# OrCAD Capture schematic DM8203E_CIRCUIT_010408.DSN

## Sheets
1 DM9162: size B; note: www.jhongtech.com    qq:441635295
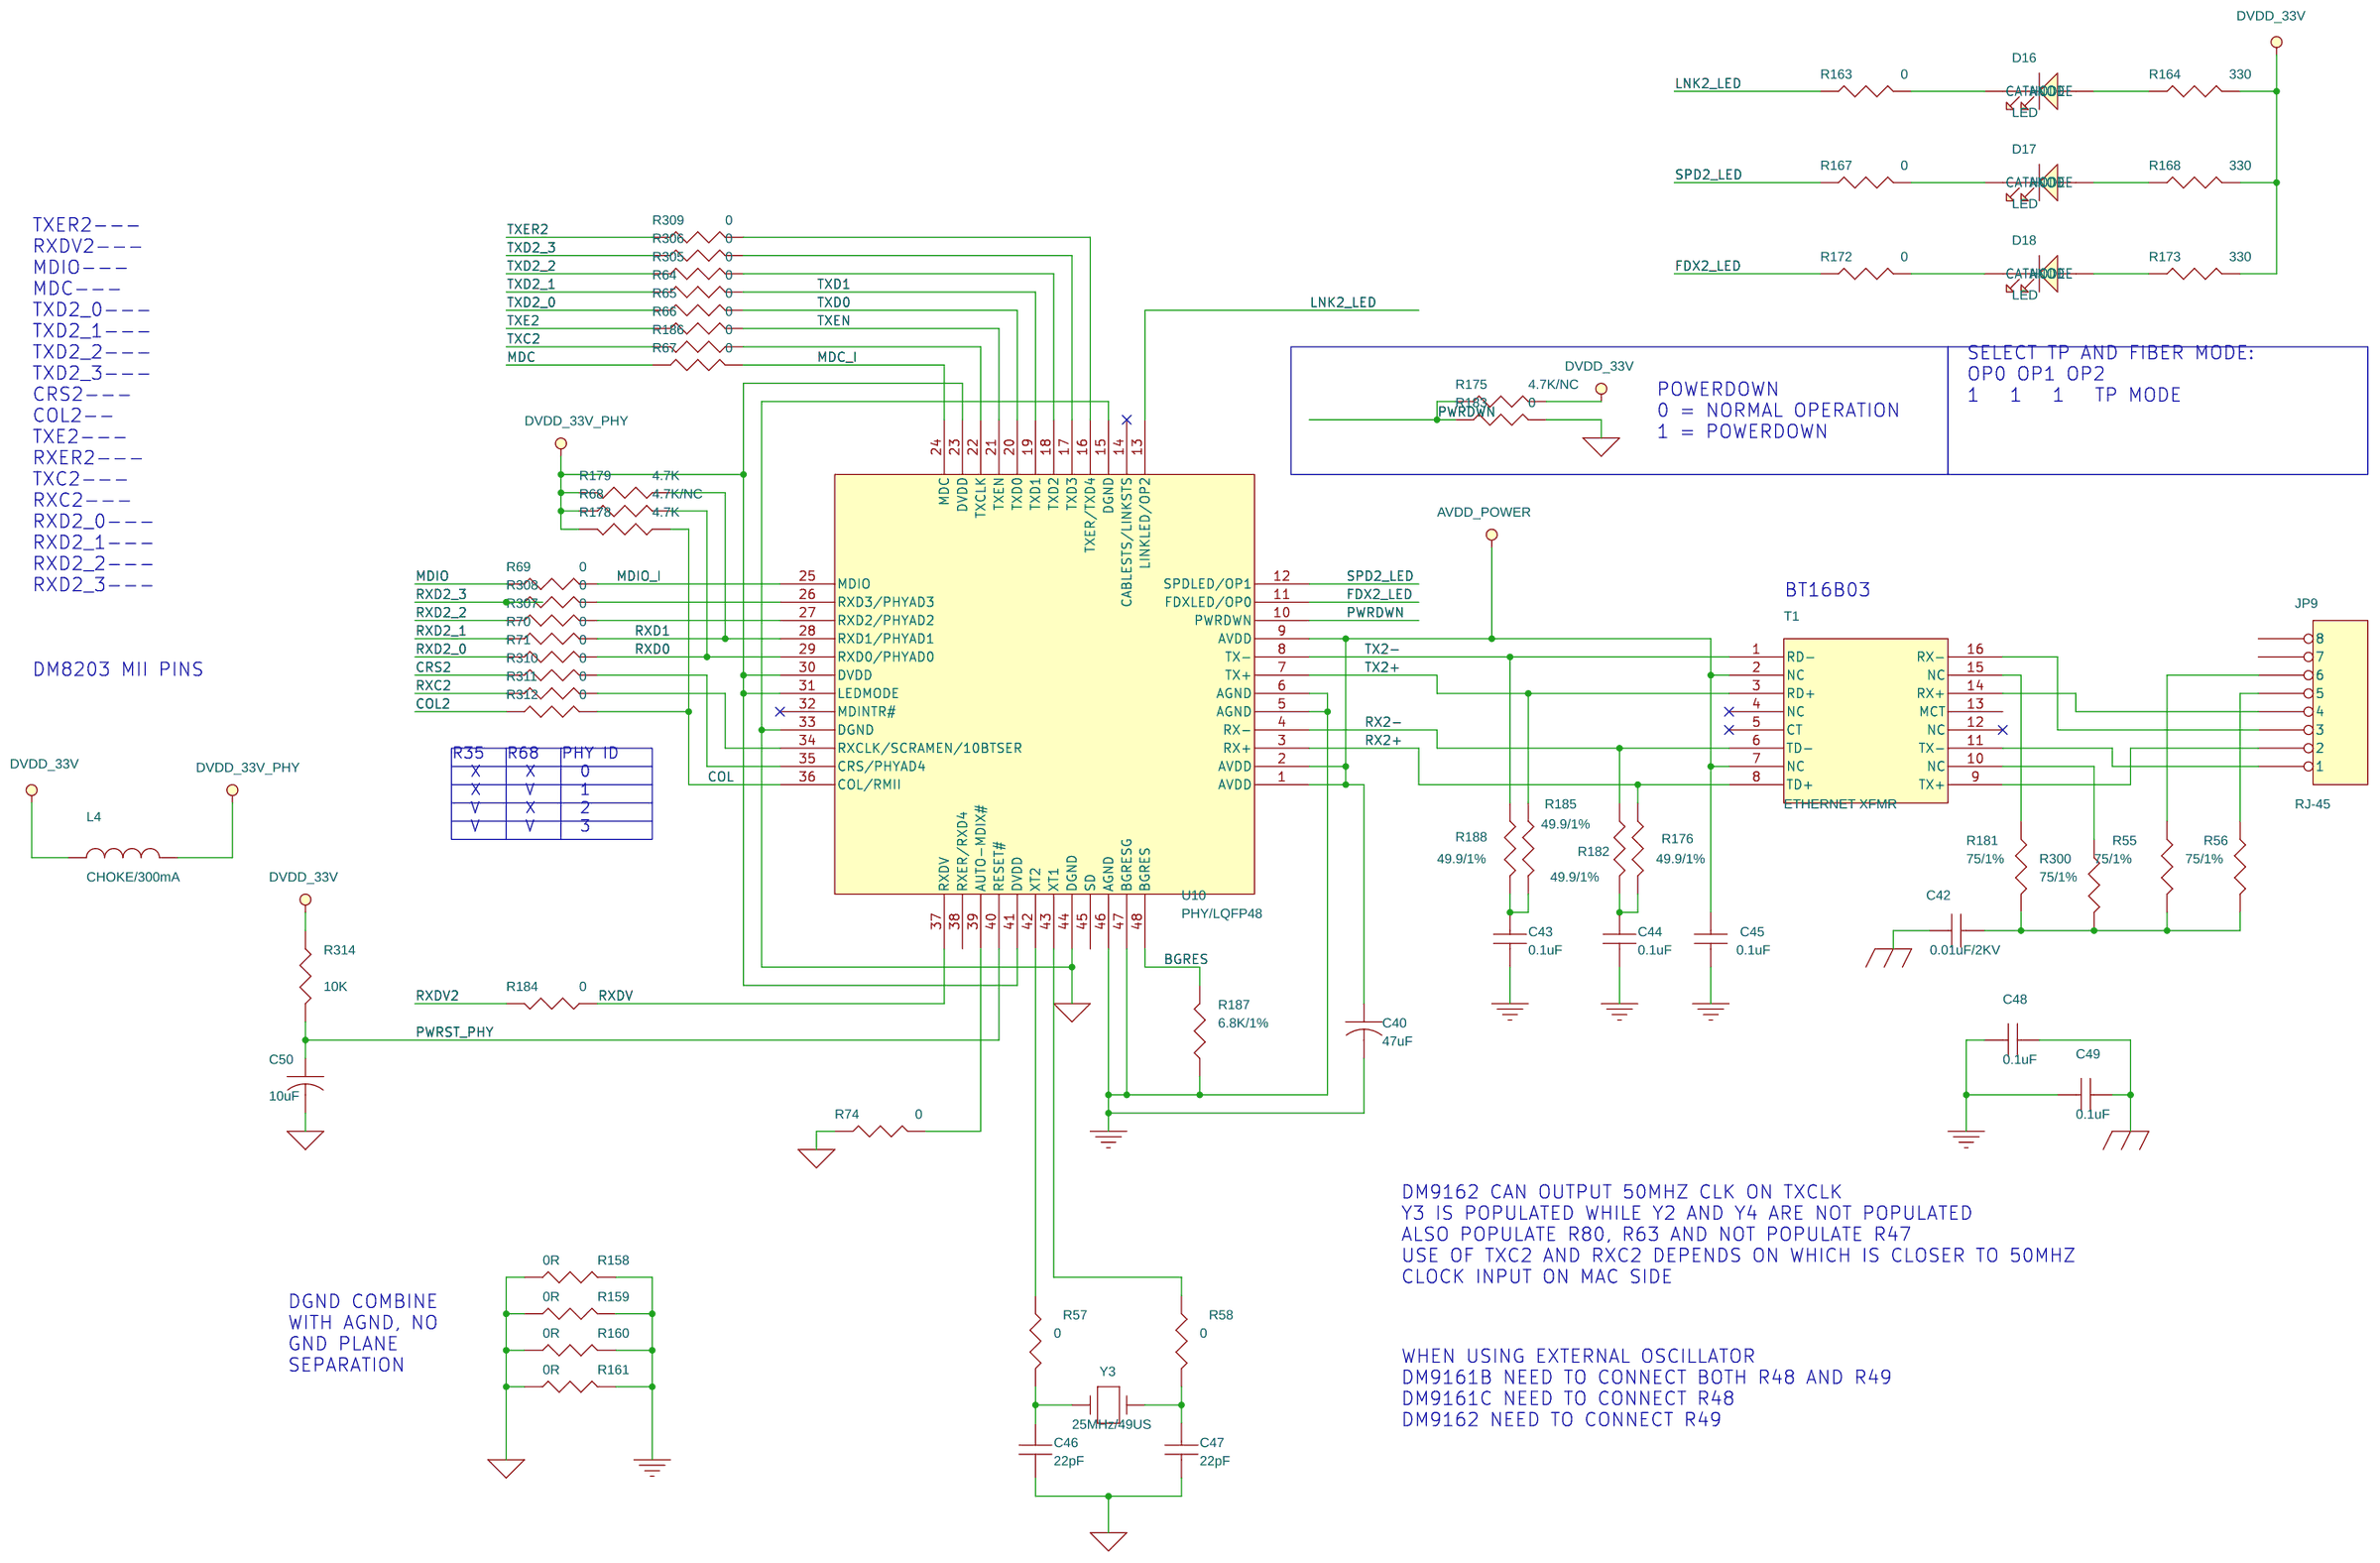
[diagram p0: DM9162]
2 DM8203E EVB V2.1: size B; title: DM8203E_EVB; rev: 2.0; note: www.jhongtech.com  QQ:441635295
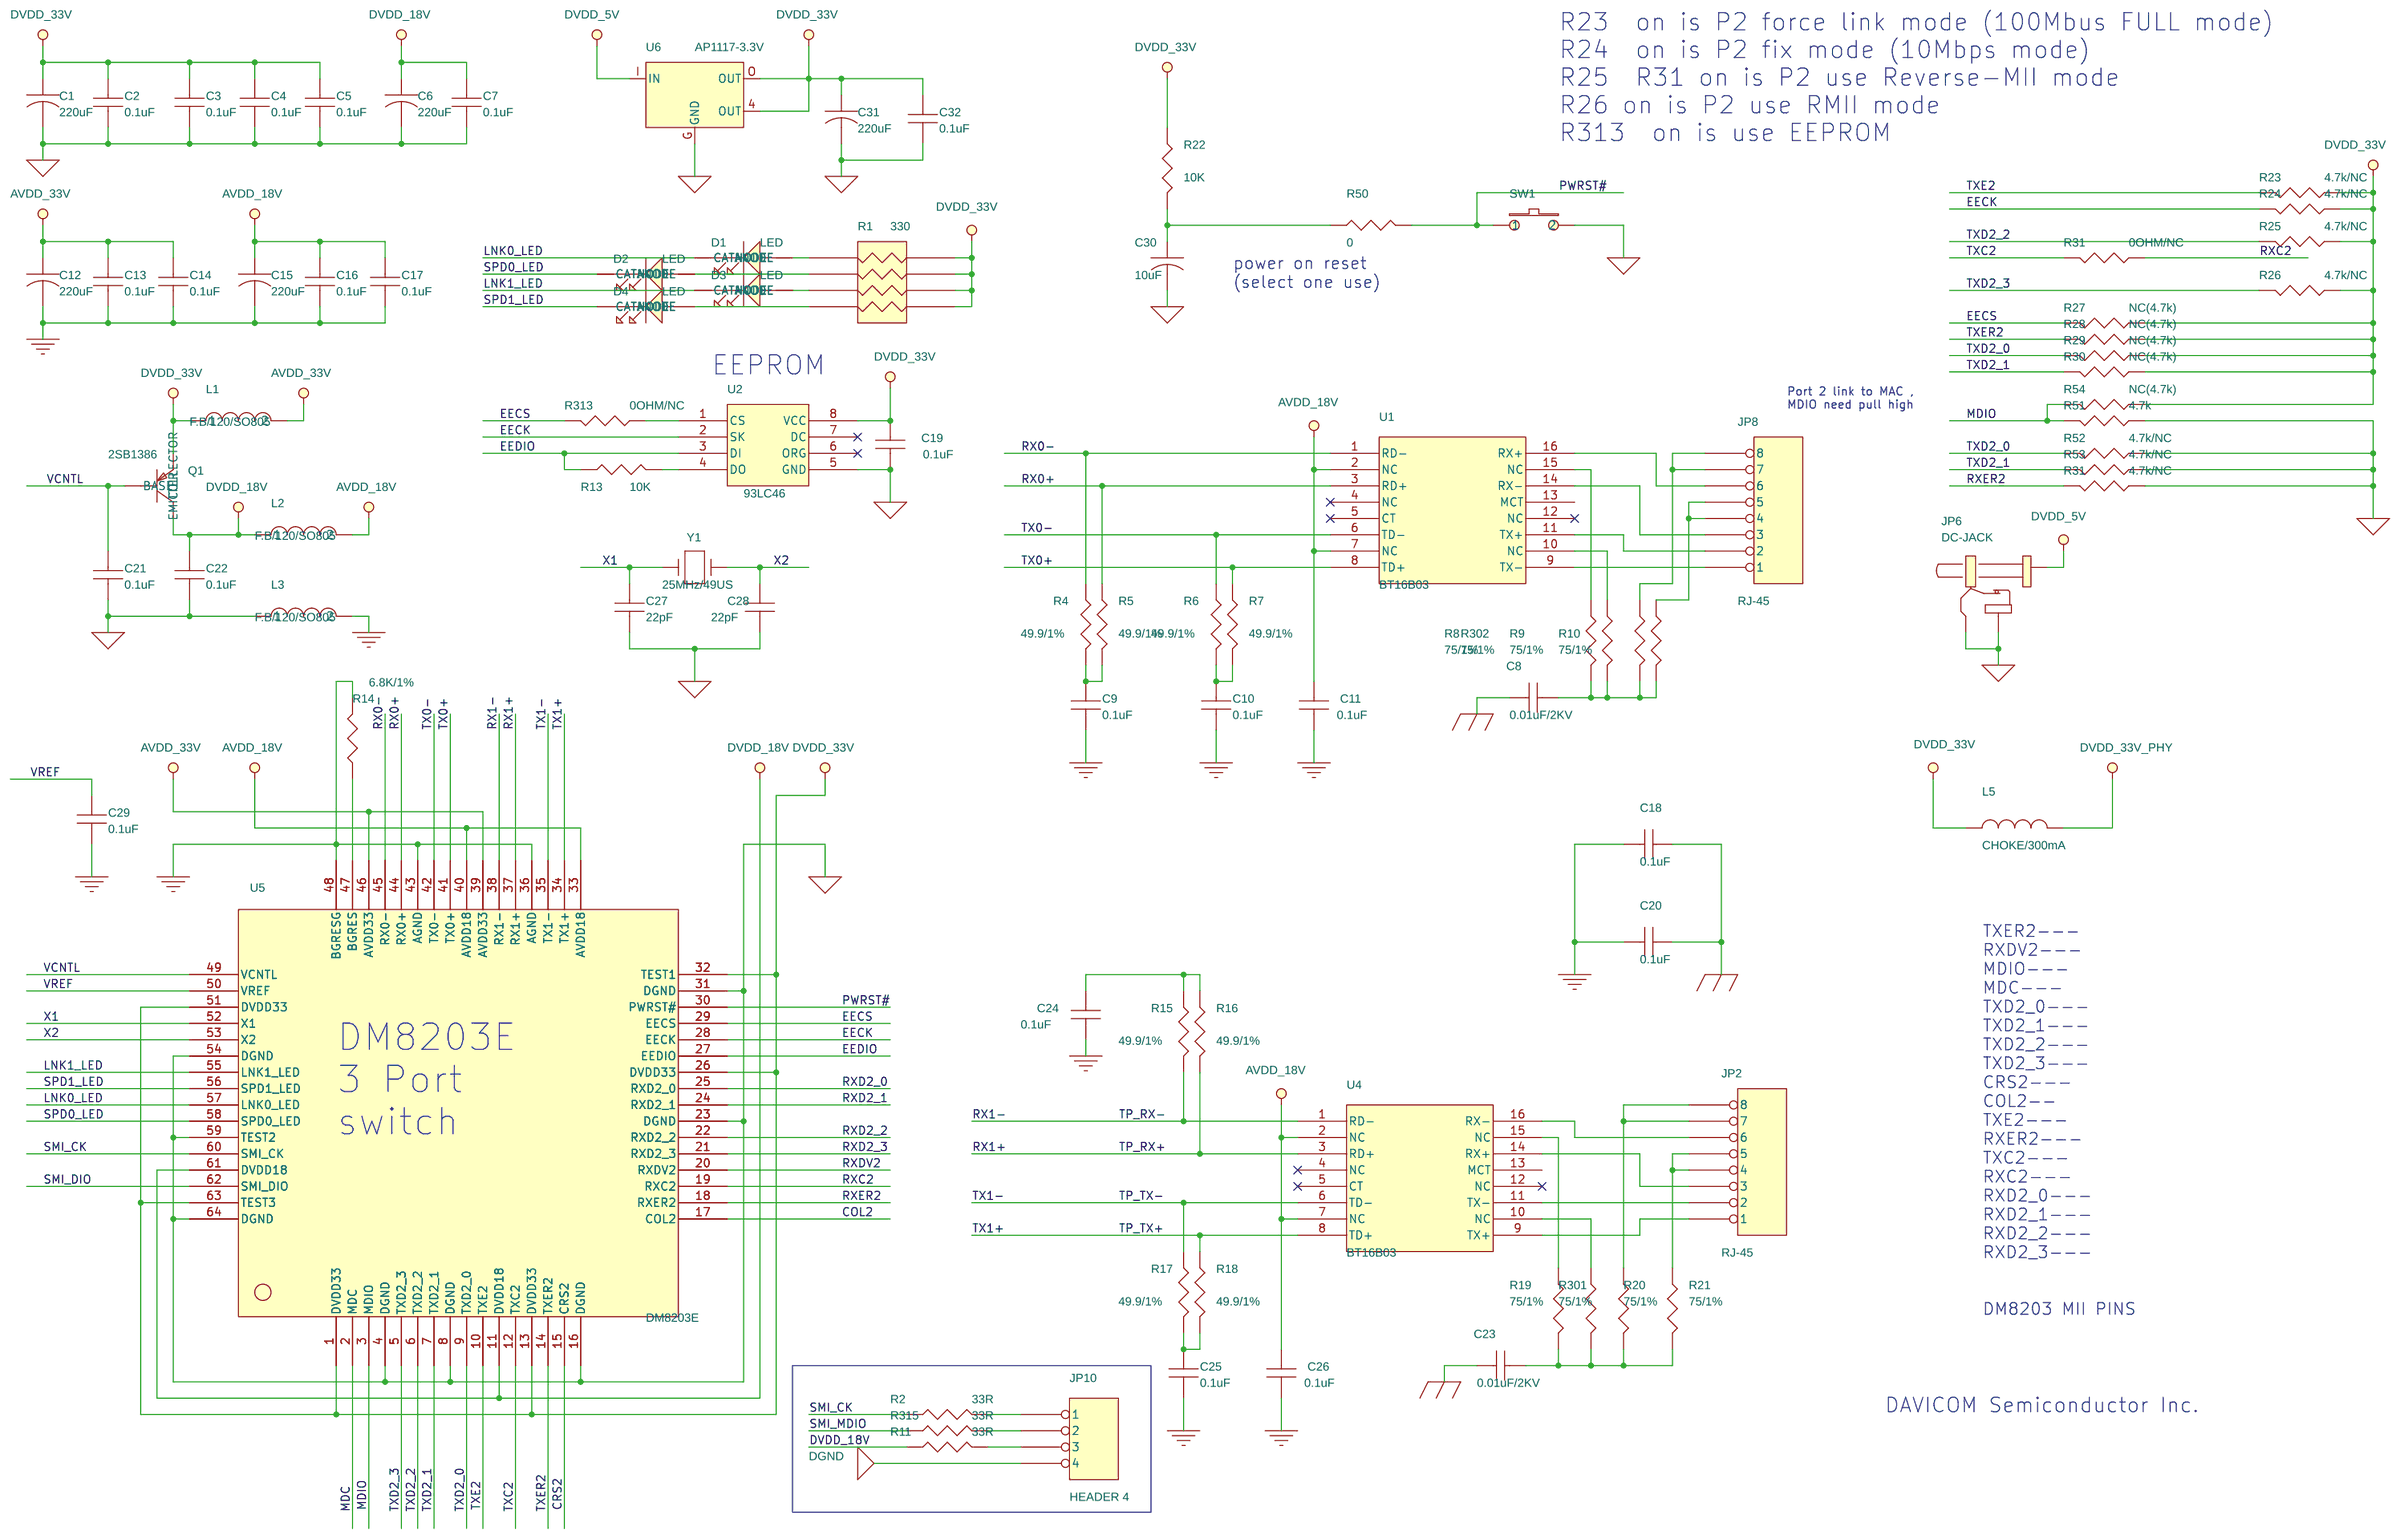
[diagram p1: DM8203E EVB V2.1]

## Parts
sheet DM8203E EVB V2.1
C1  220uF  [EC-MR05-2.5]
C2  0.1uF  [c0603]
C3  0.1uF  [c0603]
C4  0.1uF  [c0603]
C5  0.1uF  [c0603]
C6  220uF  [EC-MR05-2.5]
C7  0.1uF  [c0603]
C8  0.01uF/2KV  [C-10-03-7.5-5]
C9  0.1uF  [C0603]
C10  0.1uF  [C0603]
C11  0.1uF  [C0603]
C12  220uF  [EC-MR05-2.5]
C13  0.1uF  [c0603]
C14  0.1uF  [c0603]
C15  220uF  [EC-MR05-2.5]
C16  0.1uF  [c0603]
C17  0.1uF  [c0603]
C18  0.1uF  [C0603]
C19  0.1uF  [c0603]
C20  0.1uF  [C0603]
C21  0.1uF  [c0603]
C22  0.1uF  [c0603]
C23  0.01uF/2KV  [C-10-03-7.5-5]
C24  0.1uF  [C0603]
C25  0.1uF  [C0603]
C26  0.1uF  [C0603]
C27  22pF  [c0603]
C28  22pF  [c0603]
C29  0.1uF  [c0603]
C30  10uF  [EC-MR05-2.5]
C31  220uF  [EC-MR05-2.5]
C32  0.1uF  [c0603]
D1  LED  [LED]
D2  LED  [LED]
D3  LED  [LED]
D4  LED  [LED]
JP2  RJ-45  [RJ45]
JP6  DC-JACK  [DCJACK]
JP8  RJ-45  [RJ45]
JP10  HEADER 4  [CON4_SIP-2.54]
L1  F.B/120/SO805  [L0805]
L2  F.B/120/SO805  [L0805]
L3  F.B/120/SO805  [L0805]
L5  CHOKE/300mA  [R1206]
Q1  2SB1386  [SC62]
R1  330  [8p4r-a1]
R2  33R  [R0603]
R4  49.9/1%  [R0603]
R5  49.9/1%  [R0603]
R6  49.9/1%  [R0603]
R7  49.9/1%  [R0603]
R8  75/1%  [R0603]
R9  75/1%  [R0603]
R10  75/1%  [R0603]
R11  33R  [R0603]
R13  10K  [R0603]
R14  6.8K/1%  [R0603]
R15  49.9/1%  [R0603]
R16  49.9/1%  [R0603]
R17  49.9/1%  [R0603]
R18  49.9/1%  [R0603]
R19  75/1%  [R0603]
R20  75/1%  [R0603]
R21  75/1%  [R0603]
R22  10K  [R0603]
R23  4.7k/NC  [R0603]
R24  4.7k/NC  [R0603]
R25  4.7k/NC  [R0603]
R26  4.7k/NC  [R0603]
R27  NC(4.7k)  [R0603]
R28  NC(4.7k)  [R0603]
R29  NC(4.7k)  [R0603]
R30  NC(4.7k)  [R0603]
R31  0OHM/NC  [R0603]
R31#2  4.7k/NC  [R0603]
R50  0  [R0603]
R51  4.7k  [R0603]
R52  4.7k/NC  [R0603]
R53  4.7k/NC  [R0603]
R54  NC(4.7k)  [R0603]
R301  75/1%  [R0603]
R302  75/1%  [R0603]
R313  0OHM/NC  [R0603]
R315  33R  [R0603]
SW1  RESET_BUTTON  [SW-1102]
U1  BT16B03  [PH163539]
U2  93LC46  [DIP8]
U4  BT16B03  [PH163539]
U5  DM8203E  [LQFP64-1212-.5]
U6  AP1117-3.3V  [SOT223]
Y1  25MHz/49US  [49us]
sheet DM9162
C40  47uF  [EC-MR05-2.5]
C42  0.01uF/2KV  [C-10-03-7.5-5]
C43  0.1uF  [C0603]
C44  0.1uF  [C0603]
C45  0.1uF  [C0603]
C46  22pF  [c0603]
C47  22pF  [c0603]
C48  0.1uF  [C0603]
C49  0.1uF  [C0603]
C50  10uF  [EC-MR05-2.5]
D16  LED  [LED_AK]
D17  LED  [LED_AK]
D18  LED  [LED_AK]
JP9  RJ-45  [RJ45]
L4  CHOKE/300mA  [R1206]
R55  75/1%  [R0603]
R56  75/1%  [R0603]
R57  0  [R0603]
R58  0  [R0603]
R64  0  [R0603]
R65  0  [R0603]
R66  0  [R0603]
R67  0  [R0603]
R68  4.7K/NC  [R0603]
R69  0  [R0603]
R70  0  [R0603]
R71  0  [R0603]
R74  0  [R0603]
R158  0R  [R0805]
R159  0R  [R0805]
R160  0R  [R0805]
R161  0R  [R0805]
R163  0  [R0603]
R164  330
R167  0  [R0603]
R168  330
R172  0  [R0603]
R173  330
R175  4.7K/NC  [R0603]
R176  49.9/1%  [R0603]
R178  4.7K  [R0603]
R179  4.7K  [R0603]
R181  75/1%  [R0603]
R182  49.9/1%  [R0603]
R183  0  [R0603]
R184  0  [R0603]
R185  49.9/1%  [R0603]
R186  0  [R0603]
R187  6.8K/1%  [R0603]
R188  49.9/1%  [R0603]
R300  75/1%  [R0603]
R305  0  [R0603]
R306  0  [R0603]
R307  0  [R0603]
R308  0  [R0603]
R309  0  [R0603]
R310  0  [R0603]
R311  0  [R0603]
R312  0  [R0603]
R314  10K  [R0603]
T1  ETHERNET XFMR  [PH163539]
U10  PHY/LQFP48  [DM9161(A/B)/LQFP48]
Y3  25MHz/49US  [49us]

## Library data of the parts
C1 C6 C12 C15 C30 C31 C40 C50 = C
C2-C5 C7 C9-C11 C13 C14 C16-C18 C20-C22 C24-C26 C29 C43-C45 C48 C49 = CAP_NP
C8 C23 C42 = CAP_NP: 1ST PART FIELD: CE
C19 C27 C28 C32 C46 C47 = CAPACITOR_NON-POL
D1-D4 = LED_0
JP2 JP9 = HEADER_8: 1ST PART FIELD: RJ8-45
JP6 = PJACK21_0: 3RD PART FIELD: DCIN; Package Type: 1; Part Number: 119211-005; Schematic Symbol: SIP3P
JP8 = HEADER_8_1: 1ST PART FIELD: RJ8-45
JP10 = HEADER_8_0
L1 = INDUCTOR_1
L2 = INDUCTOR_2
L3 = INDUCTOR
L4 L5 = CHOKE
Q1 = PNP_0
R1 = RESISTOR_DIP_4
R2 R4-R11 R13-R31 R31#2 R50-R58 R64-R71 R74 R158-R161 R163 R164 R167 R168 R172 R173 R175 R176 R178 R179 R181-R188 R300-R302 R305-R315 = R
SW1 = SW_PUSHBUTTON_0: Package Type: 1
U1 = MIM_6: 1ST PART FIELD: YCL0303
U2 = 93C46_2
U4 = MIM_5: 1ST PART FIELD: YCL0303
U5 = DM9013E_3
U6 = 1117-3_0.3_v2
Y1 = CRYSTAL_0
D16-D18 = LED_6
T1 = MIM_0: 1ST PART FIELD: YCL0303
U10 = DM9118_0
Y3 = CRYSTAL

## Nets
AGND: C9.2 C10.2 C11.2 C12.2 C13.2 C14.2 C15.2 C16.2 C17.2 C18.2 C20.2 C24.2 C25.2 C26.2 C29.2 C40.2 C43.2 C44.2 C45.2 C48.2 C49.2 L3.2 R14.2 R158.2 R159.2 R160.2 R161.2 R187.1 U5.36(AGND) U5.43(AGND) U5.48(BGRESG) U10.5(AGND) U10.6(AGND) U10.46(AGND) U10.47(BGRESG)
AVDD_18V: C11.1 C15.1 C16.1 C17.1 C26.1 L2.2 U1.2(NC) U1.7(NC) U4.2(NC) U4.7(NC) U5.33(AVDD18) U5.40(AVDD18)
AVDD_33V: C12.1 C13.1 C14.1 L1.2 U5.39(AVDD33) U5.46(AVDD33)
AVDD_POWER: C40.1 C45.1 T1.2(NC) T1.7(NC) U10.1(AVDD) U10.2(AVDD) U10.9(AVDD)
DGND: C1.2 C2.2 C3.2 C4.2 C5.2 C6.2 C7.2 C19.2 C21.2 C22.2 C27.2 C28.2 C30.2 C31.2 C32.2 C46.2 C47.2 C50.2 JP6.2 JP6.3 JP10.4 L3.1 R31#2.1 R51.1 R52.1 R53.1 R74.2 R158.1 R159.1 R160.1 R161.1 R183.1 SW1.2 U2.5(GND) U5.4(DGND) U5.8(DGND) U5.16(DGND) U5.23(DGND) U5.31(DGND) U5.54(DGND) U5.59(TEST2) U5.64(DGND) U6.G(GND) U10.15(DGND) U10.33(DGND) U10.44(DGND)
DVDD_5V: JP6.1 U6.I(IN)
DVDD_18V: C6.1 C7.1 C22.1 L2.1 Q1.C(COLLECTOR) R11.1 U5.11(DVDD18) U5.61(DVDD18)
DVDD_33V: C1.1 C2.1 C3.1 C4.1 C5.1 C19.1 C31.1 C32.1 L1.1 L4.1 L5.1 Q1.E(EMITTER) R1.5 R1.6 R1.7 R1.8 R22.1 R23.1 R24.1 R25.1 R26.1 R27.1 R28.1 R29.1 R30.1 R54.1 R164.1 R168.1 R173.1 R175.2 R314.1 U2.8(VCC) U5.1(DVDD33) U5.13(DVDD33) U5.26(DVDD33) U5.32(TEST1) U5.51(DVDD33) U5.63(TEST3) U6.4(OUT) U6.O(OUT)
DVDD_33V_PHY: L4.2 L5.2 R68.1 R178.2 R179.2 U10.23(DVDD) U10.30(DVDD) U10.31(LEDMODE) U10.41(DVDD)
BGRES: R187.2 U10.48(BGRES)
CHASIS_GND: C8.1 C18.1 C20.1 C23.1 C42.1 C48.1 C49.1
COL: R178.1 R312.2 U10.36(COL/RMII)
COL2: U5.17(COL2)
COL2 (page DM9162): R312.1
CRS2: U5.15(CRS2)
CRS2 (page DM9162): R310.1
EECK: R24.2 U2.2(SK) U5.28(EECK)
EECS: R27.2 R313.2 U5.29(EECS)
EEDIO: R13.1 U2.3(DI) U5.27(EEDIO)
FDX2_LED: R172.2 U10.11(FDXLED/OP0)
LNK0_LED: D1.C(CATHODE) U5.57(LNK0_LED)
LNK1_LED: D3.C(CATHODE) U5.55(LNK1_LED)
LNK2_LED: R163.2 U10.13(LINKLED/OP2)
MDC: U5.2(MDC)
MDC (page DM9162): R67.1
MDC_I: R67.2 U10.24(MDC)
MDIO: R51.2 R54.2 U5.3(MDIO)
MDIO (page DM9162): R69.1
MDIO_I: R69.2 U10.25(MDIO)
PWRDWN: R175.1 R183.2 U10.10(PWRDWN)
PWRST#: R50.2 SW1.1 U5.30(PWRST#)
PWRST_PHY: C50.1 R314.2 U10.40(RESET#)
RX0+: R5.1 U1.3(RD+) U5.44(RX0+)
RX0-: R4.1 U1.1(RD-) U5.45(RX0-)
RX1+: R16.2 U4.3(RD+) U5.37(RX1+)
RX1-: R15.2 U4.1(RD-) U5.38(RX1-)
RX2+: R176.1 T1.8(TD+) U10.3(RX+)
RX2-: R182.1 T1.6(TD-) U10.4(RX-)
RXC2: R31.1 U5.19(RXC2)
RXC2 (page DM9162): R311.1
RXD0: R68.2 R71.2 U10.29(RXD0/PHYAD0)
RXD1: R70.2 R179.1 U10.28(RXD1/PHYAD1)
RXD2_0: U5.25(RXD2_0)
RXD2_0 (page DM9162): R71.1
RXD2_1: U5.24(RXD2_1)
RXD2_1 (page DM9162): R70.1
RXD2_2: U5.22(RXD2_2)
RXD2_2 (page DM9162): R307.1
RXD2_3: U5.21(RXD2_3)
RXD2_3 (page DM9162): R308.1
RXDV: R184.1 U10.37(RXDV)
RXDV2: U5.20(RXDV2)
RXDV2 (page DM9162): R184.2
RXER2: R31#2.2 U5.18(RXER2)
SMI_CK: R2.1 U5.60(SMI_CK)
SMI_DIO: U5.62(SMI_DIO)
SMI_MDIO: R315.1
SPD0_LED: D2.C(CATHODE) U5.58(SPD0_LED)
SPD1_LED: D4.C(CATHODE) U5.56(SPD1_LED)
SPD2_LED: R167.2 U10.12(SPDLED/OP1)
TP_TX+: R18.1 U4.8(TD+) U5.34(TX1+)
TP_TX-: R17.1 U4.6(TD-) U5.35(TX1-)
TX0+: R7.1 U1.8(TD+) U5.41(TX0+)
TX0-: R6.1 U1.6(TD-) U5.42(TX0-)
TX2+: R185.1 T1.3(RD+) U10.7(TX+)
TX2-: R188.1 T1.1(RD-) U10.8(TX-)
TXC2: R31.2 U5.12(TXC2)
TXC2 (page DM9162): R186.2
TXD0: R65.2 U10.20(TXD0)
TXD1: R64.2 U10.19(TXD1)
TXD2_0: R29.2 R52.2 U5.9(TXD2_0)
TXD2_0 (page DM9162): R65.1
TXD2_1: R30.2 R53.2 U5.7(TXD2_1)
TXD2_1 (page DM9162): R64.1
TXD2_2: R25.2 U5.6(TXD2_2)
TXD2_2 (page DM9162): R305.1
TXD2_3: R26.2 U5.5(TXD2_3)
TXD2_3 (page DM9162): R306.1
TXE2: R23.2 U5.10(TXE2)
TXE2 (page DM9162): R66.1
TXEN: R66.2 U10.21(TXEN)
TXER2: R28.2 U5.14(TXER2)
TXER2 (page DM9162): R309.1
VCNTL: C21.1 Q1.B(BASE) U5.49(VCNTL)
VREF: C29.1 U5.50(VREF)
X1: C27.1 U5.52(X1) Y1.1
X2: C28.1 U5.53(X2) Y1.2
N16742545: C30.1 R22.2 R50.1
N16891330: R13.2 U2.4(DO)
N16918910: D2.A(ANODE) R1.3
N16918923: JP2.7 JP2.8 R20.1
N16918925: C8.2 R8.2 R9.2 R10.2 R302.2
N16918976: JP2.3 U4.14(RX+)
N16918997: C23.2 R19.2 R20.2 R21.2 R301.2
N16918999: JP2.1 U4.9(TX+)
N16919001: D3.A(ANODE) R1.2
N16919121: JP2.4 JP2.5 R21.1
N16919184: C10.1 R6.2 R7.2
N16919196: JP2.2 U4.11(TX-)
N16919203: JP2.6 U4.16(RX-)
N16919221: D1.A(ANODE) R1.4
N16919396: C9.1 R4.2 R5.2
N16919404: JP8.6 U1.16(RX+)
N16919500: D4.A(ANODE) R1.1
N16919506: R8.1 U1.15(NC)
N16919656: JP8.1 U1.9(TX-)
N16919664: R19.1 U4.15(NC)
N16919767: C25.1 R17.2 R18.2
N16976973: R14.1 U5.47(BGRES)
N16985444: C24.1 R15.1 R16.1
N17053030: R186.1 U10.22(TXCLK)
N17053040: C46.1 R57.2 Y3.1
N17053116: D16.A(ANODE) R164.2
N17053247: R181.1 T1.15(NC)
N17053266: R57.1 U10.42(XT2)
N17053271: C42.2 R55.2 R56.2 R181.2 R300.2
N17053289: C43.1 R185.2 R188.2
N17053317: R58.1 U10.43(XT1)
N17053337: C47.1 R58.2 Y3.2
N17053345: JP9.3 T1.16(RX-)
N17053356: R74.1 U10.39(AUTO-MDIX#)
N17053367: C44.1 R176.2 R182.2
N17053374: JP9.2 T1.9(TX+)
N17053741: D17.K(CATHODE) R167.1
N17053746: D17.A(ANODE) R168.2
N17053748: D16.K(CATHODE) R163.1
N17053753: D18.K(CATHODE) R172.1
N17053755: D18.A(ANODE) R173.2
N17058438: R300.1 T1.10(NC)
N17063024: R301.1 U4.10(NC)
N17063162: R302.1 U1.10(NC)
N17064930: R306.2 U10.17(TXD3)
N17064935: R305.2 U10.18(TXD2)
N17065028: R307.2 U10.27(RXD2/PHYAD2)
N17065031: R308.2 U10.26(RXD3/PHYAD3)
N17065597: R309.2 U10.16(TXER/TXD4)
N17065659: R310.2 U10.35(CRS/PHYAD4)
N17065739: R311.2 U10.34(RXCLK/SCRAMEN/10BTSER)
N17068184: JP8.2 U1.11(TX+)
N17068206: JP8.3 U1.14(RX-)
N17068215: JP8.7 JP8.8 R9.1
N17068218: JP8.4 JP8.5 R10.1
N17068349: R313.1 U2.1(CS)
N17068446: JP9.4 T1.14(RX+)
N17068477: JP9.1 T1.11(TX-)
N17068531: JP9.5 R56.1
N17068536: JP9.6 R55.1
N17073733: JP10.1 R2.2
N17073735: JP10.2 R315.2
N17073737: JP10.3 R11.2

Not connected (* = marked no-connect by the designer): JP9 7 8; T1 4(NC)* 5(CT)* 12(NC)* 13(MCT); U1 4(NC)* 5(CT)* 12(NC)* 13(MCT); U2 6(ORG)* 7(DC)*; U4 4(NC)* 5(CT)* 12(NC)* 13(MCT); U10 14(CABLESTS/LINKSTS)* 32(MDINTR#)* 38(RXER/RXD4) 45(SD)

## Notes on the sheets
sheet 1
- TXER2---
  RXDV2---
  MDIO---
  MDC---
  TXD2_0---
  TXD2_1---
  TXD2_2---
  TXD2_3---
  CRS2---
  COL2--
  TXE2---
  RXER2---
  TXC2---
  RXC2---
  RXD2_0---
  RXD2_1---
  RXD2_2---
  RXD2_3---
  DM8203 MII PINS
- SELECT TP AND FIBER MODE:
  OP0 OP1 OP2
  1   1   1   TP MODE
- POWERDOWN
  0 = NORMAL OPERATION
  1 = POWERDOWN
- BT16B03
- R35
- X
- R68
- X
- PHY ID
- 0
- X
- V
- 1
- V
- X
- 2
- V
- V
- 3
- DM9162 CAN OUTPUT 50MHZ CLK ON TXCLK
  Y3 IS POPULATED WHILE Y2 AND Y4 ARE NOT POPULATED
  ALSO POPULATE R80, R63 AND NOT POPULATE R47
  USE OF TXC2 AND RXC2 DEPENDS ON WHICH IS CLOSER TO 50MHZ
  CLOCK INPUT ON MAC SIDE
- DGND COMBINE
  WITH AGND, NO
  GND PLANE
  SEPARATION
- WHEN USING EXTERNAL OSCILLATOR
  DM9161B NEED TO CONNECT BOTH R48 AND R49
  DM9161C NEED TO CONNECT R48
  DM9162 NEED TO CONNECT R49
sheet 2
- R23  on is P2 force link mode (100Mbus FULL mode)
  R24  on is P2 fix mode (10Mbps mode)
  R25  R31 on is P2 use Reverse-MII mode
  R26 on is P2 use RMII mode
  R313  on is use EEPROM
- power on reset
  (select one use)
- EEPROM
- Port 2 link to MAC ,
  MDIO need pull high
- TXER2---
  RXDV2---
  MDIO---
  MDC---
  TXD2_0---
  TXD2_1---
  TXD2_2---
  TXD2_3---
  CRS2---
  COL2--
  TXE2---
  RXER2---
  TXC2---
  RXC2---
  RXD2_0---
  RXD2_1---
  RXD2_2---
  RXD2_3---
  DM8203 MII PINS
- DM8203E
  3 Port
  switch
- DAVICOM Semiconductor Inc.
